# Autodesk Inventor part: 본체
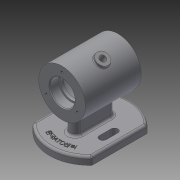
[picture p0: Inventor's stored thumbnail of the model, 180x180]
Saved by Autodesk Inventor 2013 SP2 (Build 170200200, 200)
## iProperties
Created: 2022-02
Part Number: 본체
Material: Generic
Document SubType Name: Modeling
Designer: a
Density: 1 g/cm^3
Author: a
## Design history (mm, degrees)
sketch "스케치1"
  geometry: C1 r 30 at (0, 0); 1 further point
  constraints: 1 centre point, 1 coincident
  dimensions: "d0" = 60 diameter of C1
extrude "돌출1" new body sketch "스케치1" stored distance "d1" = 72; taper "d2" = 0 deg
node "작업 평면1"
sketch "스케치2"
  geometry: L1 (38, 35.496)-(38, -35.496); L2 (-38, 35.496)-(-38, -35.496); A1 r 52 centre (0, 0) between (-38, -35.496) and (38, -35.496); A2 r 52 centre (0, 0) between (38, 35.496) and (-38, 35.496); 1 further point
  constraints: 4 end point, 4 point on circle, 2 centre point, 2 vertical, 1 coincident
  dimensions: "d5" = 76 distance between parallel lines of L2 L1; "d6" = 38 distance from line of point (0, 0) L1; "d7" = 52 radius of A1; "d8" = 52 radius of A2
extrude "돌출2" join sketch "스케치2" distance "d9" = 10; taper "d10" = 0 deg
sketch "스케치3"
  geometry: L1 (38, -35.496)-(38, 35.496) reference; L2 (-7, -19)-(-7, 19); L3 (7, -19)-(7, 19); A1 r 52 centre (0, 0) between (-38, -35.496) and (38, -35.496) reference; A2 r 7 centre (0, -19) between (-7, -19) and (7, -19); A3 r 7 centre (0, 19) between (7, 19) and (-7, 19)
  constraints: 4 end point, 4 point on circle, 3 tangent, 2 centre point, 2 parallel, 1 vertical alignment
  dimensions: "d11" = 14 diameter of A2; "d12" = 14 diameter of A3; "d13" = 38 distance of A3.centre A2.centre; "d14" = 19 distance of A1.centre A3.centre
extrude "돌출3" join sketch "스케치3" stored distance "d15" = 10; taper "d16" = 0 deg
sketch "스케치4"
  geometry: L1 (0, 36)-(0, -36); L2 (30, 36)-(-30, 36) reference; L3 (-30, -36)-(30, -36) reference; L4 (0, 36)-(16, 36); L5 (16, 36)-(16, 24); L6 (16, 24)-(14, 24); L7 (14, 24)-(14, 20); L8 (14, 20)-(25, 20); L9 (25, 20)-(25, -20); L10 (25, -20)-(14, -20); L11 (14, -20)-(14, -24); L12 (14, -24)-(16, -24); L13 (16, -24)-(16, -36); L14 (0, -36)-(16, -36); 2 further points
  constraints: 24 end point, 6 parallel, 4 perpendicular, 3 midpoint, 2 point on line, 1 coincident, 1 vertical
  dimensions: "d17" = 12 distance between parallel lines of L6 L4; "d19" = 40 distance between parallel lines of L10 L8; "d20" = 12 distance between parallel lines of L3 L12; "d21" = 32 diameter of L5 L1; "d22" = 28 diameter of L7 L1; "d23" = 50 diameter of L9 L1; "d24" = 32 diameter of L13 L1; "d25" = 28 diameter of L11 L1; "d26" = 4 distance between parallel lines of L12 L10
revolve "회전1" sketch "스케치4" stored, may be unused: angle "d27" = 90 deg
fillet "모깎기1" dims "d28" = 0.3
sketch "스케치5"
  geometry: L1 (0, 0)-(16.5, 28.579); L2 (0, 0)-(0, 17.884)
  constraints: 4 end point, 1 vertical
  dimensions: "d29" = 33 distance of L1.start L1.end; "d31" = 30 deg angle of L1 L2
node "작업 평면2"
sketch "스케치6"
  geometry: C1 r 8 at (0, 0); 1 further point
  constraints: 1 centre point, 1 coincident
  dimensions: "d32" = 16 diameter of C1
extrude "돌출4" join sketch "스케치6" distance "d33" = 5.08966; taper "d34" = 0 deg
sketch "스케치7"
  geometry: C1 r 8 at (0, 0) reference; C2 r 4 at (0, 0)
  constraints: 1 centre point, 1 coincident
  dimensions: "d35" = 8 diameter of C2
extrude "돌출5" cut sketch "스케치7" distance "d36" = 25.58966; taper "d37" = 0 deg
fillet "모깎기2" dims "d38" = 1
sketch "스케치8"
  geometry: L1 (38, -35.496)-(38, 35.496) reference; L2 (-28.5, -7.5)-(-28.5, 7.5); L3 (-19.5, -7.5)-(-19.5, 7.5); A1 r 7 centre (0, 19) between (7, 19) and (-7, 19) reference; A2 r 52 centre (0, 0) between (-38, -35.496) and (38, -35.496) reference; A3 r 4.5 centre (-24, -7.5) between (-28.5, -7.5) and (-19.5, -7.5); A4 r 4.5 centre (-24, 7.5) between (-19.5, 7.5) and (-28.5, 7.5)
  constraints: 4 end point, 4 point on circle, 3 tangent, 2 centre point, 2 parallel
  dimensions: "d39" = 9 diameter of A3; "d40" = 9 diameter of A4; "d41" = 24 horizontal distance of A1.centre A4.centre; "d42" = 15 distance of A4.centre A3.centre; "d43" = 7.5 vertical distance of A2.centre A4.centre
extrude "돌출6" cut sketch "스케치8" stored distance "d44" = 25.58966; taper "d45" = 0 deg
sketch "스케치9"
  geometry: C1 r 42.5 at (0, 0); A1 r 52 centre (0, 0) between (38, 35.496) and (-38, 35.496) reference
  constraints: 1 centre point, 1 coincident, 1 other
  dimensions: "d46" = 85 diameter of C1
feature "엠보싱1" sketch "스케치9" dims "d13" = 38, "d47" = 0.5, "d48" = 0
fillet "모깎기3" dims "d49" = 3
fillet "모깎기4" dims "d50" = 3
fillet "모깎기5" dims "d51" = 3
fillet "모깎기6" dims "d52" = 3
sketch "스케치10"
  geometry: C1 r 16 at (0, 0) reference; 1 further point
  constraints: 1 vertical alignment
  dimensions: "d53" = 23 distance of C1.centre point (0, 23)
hole "구멍1" sketch "스케치10" at (0, 23) diameter "d54" = 3.242; stored, may be unused: countersink angle "d58" = 90 deg, drill point angle "d60" = 118 deg; dims "d55" = 8, "d56" = 4, "d57" = 2, "d59" = 10
chamfer "모따기1" distance "d64" = 1; stored, may be unused: second distance "d65" = 2, angle "d66" = 45 deg
fillet "모깎기7" dims "d67" = 3
node "솔리드1"
mirror "대칭1"
pattern_circular "원형 패턴1" dims angle "d62" = 360 deg
mirror "대칭2"
other parameters: "d3" = -62, "d4" = 104
